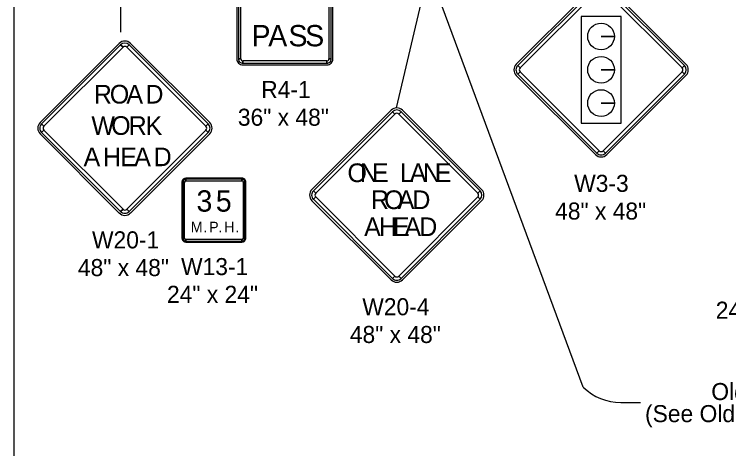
# Model space of a CAD drawing. Extents: x -2134934 to -2119606, y -2139046 to -2137036.
# Drawn here: x -2130232 to -2129562, y -2138285 to -2137877 of the extents above; entities that cross this region are included whole.
import ezdxf

# ---------------------------------------------------------------- set-up
doc = ezdxf.new("R2010")
doc.units = 0
for name, color, linetype in [('Default', 7, 'Continuous'), ('dsnStdLabel', 7, 'Continuous'), ('Level 2', 7, 'Continuous')]:
    doc.layers.add(name, color=color, linetype=linetype)

msp = doc.modelspace()

# ---------------------------------------------------------------- linework, layer by layer
at = {"layer": 'Default'}
msp.add_lwpolyline([(-2130231.95, -2137035.95), (-2127096.96, -2137035.95), (-2127096.96, -2139045.94), (-2130231.95, -2139045.94)], close=True, dxfattribs=at)
at = {"layer": 'dsnStdLabel'}
for p, q in [((-2130023.24, -2137810.29), (-2130023.24, -2137919.04)), ((-2129933.24, -2137919.04), (-2129933.24, -2137810.29)), ((-2129686.95, -2137849.65), (-2129761.19, -2137923.9)), ((-2129602.1, -2137923.9), (-2129676.34, -2137849.65)), ((-2129669.24, -2137897.87), (-2129681.74, -2137897.87)), ((-2129681.74, -2137897.87), (-2129669.24, -2137897.87)), ((-2130133.53, -2137904.4), (-2130207.78, -2137978.64)), ((-2130048.68, -2137978.64), (-2130122.92, -2137904.4)), ((-2130132.2, -2137905.72), (-2130129.99, -2137907.93)), ((-2130126.46, -2137907.93), (-2130124.25, -2137905.72)), ((-2130019.49, -2137919.04), (-2130021.68, -2137919.04)), ((-2130017.62, -2137923.1), (-2130017.62, -2137920.91)), ((-2130017.62, -2137924.66), (-2129938.87, -2137924.66)), ((-2129938.87, -2137920.91), (-2129938.87, -2137923.1)), ((-2129934.81, -2137919.04), (-2129936.99, -2137919.04)), ((-2129757.66, -2137927.43), (-2129759.87, -2137925.22)), ((-2129759.87, -2137933.18), (-2129757.66, -2137930.97)), ((-2129669.24, -2137929.12), (-2129681.74, -2137929.12)), ((-2129681.74, -2137929.12), (-2129669.24, -2137929.12)), ((-2129603.42, -2137925.22), (-2129605.63, -2137927.43)), ((-2129605.63, -2137930.97), (-2129603.42, -2137933.18)), ((-2129761.19, -2137934.5), (-2129686.95, -2138008.75)), ((-2129676.34, -2138008.75), (-2129602.1, -2137934.5)), ((-2129669.24, -2137960.37), (-2129681.74, -2137960.37)), ((-2129681.74, -2137960.37), (-2129669.24, -2137960.37)), ((-2129878.55, -2137967.13), (-2129952.8, -2138041.38)), ((-2129877.23, -2137968.46), (-2129875.02, -2137970.67)), ((-2129871.48, -2137970.67), (-2129869.27, -2137968.46)), ((-2129793.7, -2138041.38), (-2129867.95, -2137967.13)), ((-2130204.24, -2137982.18), (-2130206.45, -2137979.97)), ((-2130050, -2137979.97), (-2130052.21, -2137982.18)), ((-2130207.78, -2137989.25), (-2130133.53, -2138063.5)), ((-2130206.45, -2137987.92), (-2130204.24, -2137985.71)), ((-2130122.92, -2138063.5), (-2130048.68, -2137989.25)), ((-2130052.21, -2137985.71), (-2130050, -2137987.92)), ((-2129683.41, -2138005.21), (-2129685.62, -2138007.42)), ((-2129677.67, -2138007.42), (-2129679.88, -2138005.21)), ((-2130018.46, -2138030.77), (-2130070.95, -2138030.77)), ((-2130070.95, -2138033.27), (-2130070.95, -2138031.71)), ((-2130018.46, -2138031.71), (-2130018.46, -2138033.27)), ((-2130074.7, -2138034.52), (-2130074.7, -2138087.02)), ((-2130073.77, -2138034.52), (-2130072.2, -2138034.52)), ((-2130017.21, -2138034.52), (-2130015.64, -2138034.52)), ((-2130014.71, -2138087.02), (-2130014.71, -2138034.52)), ((-2129949.26, -2138044.91), (-2129951.47, -2138042.7)), ((-2129795.03, -2138042.7), (-2129797.23, -2138044.91)), ((-2129952.8, -2138051.98), (-2129878.55, -2138126.23)), ((-2129951.47, -2138050.66), (-2129949.26, -2138048.45)), ((-2129867.95, -2138126.23), (-2129793.7, -2138051.98)), ((-2129797.23, -2138048.45), (-2129795.03, -2138050.66)), ((-2130129.99, -2138059.96), (-2130132.2, -2138062.17)), ((-2130124.25, -2138062.17), (-2130126.46, -2138059.96)), ((-2130072.2, -2138087.02), (-2130073.77, -2138087.02)), ((-2130070.95, -2138089.83), (-2130070.95, -2138088.27)), ((-2130070.95, -2138090.77), (-2130018.46, -2138090.77)), ((-2130018.46, -2138088.27), (-2130018.46, -2138089.83)), ((-2130015.64, -2138087.02), (-2130017.21, -2138087.02)), ((-2129875.02, -2138122.69), (-2129877.23, -2138124.9)), ((-2129869.27, -2138124.9), (-2129871.48, -2138122.69))]:
    msp.add_line(p, q, dxfattribs=at)
for points in [[(-2130021.68, -2137810.29), (-2130021.68, -2137919.04), (-2130019.49, -2137919.04), (-2130019.49, -2137810.29), (-2130021.68, -2137810.29)], [(-2129934.81, -2137919.04), (-2129934.81, -2137810.29), (-2129936.99, -2137810.29), (-2129936.99, -2137919.04), (-2129934.81, -2137919.04)], [(-2129685.62, -2137850.98), (-2129759.87, -2137925.22), (-2129757.66, -2137927.43), (-2129683.41, -2137853.19), (-2129685.62, -2137850.98)], [(-2129603.42, -2137925.22), (-2129677.67, -2137850.98), (-2129679.88, -2137853.19), (-2129605.63, -2137927.43), (-2129603.42, -2137925.22)], [(-2129662.91, -2137879.26), (-2129700.38, -2137879.26), (-2129700.38, -2137979.15), (-2129662.91, -2137979.15), (-2129662.91, -2137879.26)], [(-2130132.2, -2137905.72), (-2130206.45, -2137979.97), (-2130204.24, -2137982.18), (-2130129.99, -2137907.93), (-2130132.2, -2137905.72)], [(-2130050, -2137979.97), (-2130124.25, -2137905.72), (-2130126.46, -2137907.93), (-2130052.21, -2137982.18), (-2130050, -2137979.97)], [(-2130017.62, -2137923.1), (-2129938.87, -2137923.1), (-2129938.87, -2137920.91), (-2130017.62, -2137920.91), (-2130017.62, -2137923.1)], [(-2129759.87, -2137933.18), (-2129685.62, -2138007.42), (-2129683.41, -2138005.21), (-2129757.66, -2137930.97), (-2129759.87, -2137933.18)], [(-2129677.67, -2138007.42), (-2129603.42, -2137933.18), (-2129605.63, -2137930.97), (-2129679.88, -2138005.21), (-2129677.67, -2138007.42)], [(-2129877.23, -2137968.46), (-2129951.47, -2138042.7), (-2129949.26, -2138044.91), (-2129875.02, -2137970.67), (-2129877.23, -2137968.46)], [(-2129795.03, -2138042.7), (-2129869.27, -2137968.46), (-2129871.48, -2137970.67), (-2129797.23, -2138044.91), (-2129795.03, -2138042.7)], [(-2130206.45, -2137987.92), (-2130132.2, -2138062.17), (-2130129.99, -2138059.96), (-2130204.24, -2137985.71), (-2130206.45, -2137987.92)], [(-2130124.25, -2138062.17), (-2130050, -2137987.92), (-2130052.21, -2137985.71), (-2130126.46, -2138059.96), (-2130124.25, -2138062.17)], [(-2130018.46, -2138031.71), (-2130070.95, -2138031.71), (-2130070.95, -2138033.27), (-2130018.46, -2138033.27), (-2130018.46, -2138031.71)], [(-2130073.77, -2138034.52), (-2130073.77, -2138087.02), (-2130072.2, -2138087.02), (-2130072.2, -2138034.52), (-2130073.77, -2138034.52)], [(-2130015.64, -2138087.02), (-2130015.64, -2138034.52), (-2130017.21, -2138034.52), (-2130017.21, -2138087.02), (-2130015.64, -2138087.02)], [(-2129951.47, -2138050.66), (-2129877.23, -2138124.9), (-2129875.02, -2138122.69), (-2129949.26, -2138048.45), (-2129951.47, -2138050.66)], [(-2129869.27, -2138124.9), (-2129795.03, -2138050.66), (-2129797.23, -2138048.45), (-2129871.48, -2138122.69), (-2129869.27, -2138124.9)], [(-2130070.95, -2138089.83), (-2130018.46, -2138089.83), (-2130018.46, -2138088.27), (-2130070.95, -2138088.27), (-2130070.95, -2138089.83)]]:
    msp.add_lwpolyline(points, close=True, dxfattribs=at)
for centre in [(-2129681.74, -2137897.87), (-2129681.74, -2137929.12), (-2129681.74, -2137960.37)]:
    msp.add_circle(centre, 12.5, dxfattribs=at)
for centre, radius, start, end in [((-2130128.23, -2137909.7), 7.5, 44.99999, 134.99974), ((-2130128.23, -2137909.7), 5.62, 44.99999, 134.99974), ((-2130128.23, -2137909.7), 2.5, 44.99999, 134.99974), ((-2130017.62, -2137919.04), 5.62, 179.99985, 270.00006), ((-2130017.62, -2137919.04), 4.06, 179.99985, 270.00006), ((-2130017.62, -2137919.04), 1.87, 179.99985, 270.00006), ((-2129938.87, -2137919.04), 5.62, 270.00006, 0.00027), ((-2129938.87, -2137919.04), 4.06, 270.00006, 0.00027), ((-2129938.87, -2137919.04), 1.87, 270.00006, 0.00027), ((-2129755.89, -2137929.2), 7.5, 134.99974, 224.99995), ((-2129607.4, -2137929.2), 7.5, 315.00016, 44.9998), ((-2129755.89, -2137929.2), 5.62, 134.99974, 224.99995), ((-2129755.89, -2137929.2), 2.5, 134.99974, 224.99995), ((-2129607.4, -2137929.2), 2.5, 315.00016, 44.9998), ((-2129607.4, -2137929.2), 5.62, 315.00016, 44.9998), ((-2129873.25, -2137972.43), 7.5, 44.99999, 134.99974), ((-2129873.25, -2137972.43), 5.62, 44.99999, 134.99974), ((-2129873.25, -2137972.43), 2.5, 44.99999, 134.99974), ((-2130202.47, -2137983.95), 7.5, 134.99974, 224.99995), ((-2130202.47, -2137983.95), 5.62, 134.99974, 224.99995), ((-2130202.47, -2137983.95), 2.5, 134.99974, 224.99995), ((-2130053.98, -2137983.95), 2.5, 315.00016, 44.9998), ((-2130053.98, -2137983.95), 5.62, 315.00016, 44.9998), ((-2130053.98, -2137983.95), 7.5, 315.00016, 44.9998), ((-2129681.64, -2138003.45), 7.5, 224.99995, 315.00016), ((-2129681.64, -2138003.45), 5.62, 224.99995, 315.00016), ((-2129681.64, -2138003.45), 2.5, 224.99995, 315.00016), ((-2130070.95, -2138034.52), 3.75, 90.00021, 179.99985), ((-2130070.95, -2138034.52), 2.81, 90.00021, 179.99985), ((-2130018.46, -2138034.52), 3.75, 0, 90.00021), ((-2130018.46, -2138034.52), 2.81, 0, 90.00021), ((-2130070.95, -2138034.52), 1.25, 90.00021, 179.99985), ((-2130018.46, -2138034.52), 1.25, 0, 90.00021), ((-2129947.49, -2138046.68), 7.5, 134.99974, 224.99995), ((-2129947.49, -2138046.68), 5.62, 134.99974, 224.99995), ((-2129947.49, -2138046.68), 2.5, 134.99974, 224.99995), ((-2129799, -2138046.68), 2.5, 315.00016, 44.9998), ((-2129799, -2138046.68), 5.62, 315.00016, 44.9998), ((-2129799, -2138046.68), 7.5, 315.00016, 44.9998), ((-2130128.23, -2138058.19), 7.5, 224.99995, 315.00016), ((-2130128.23, -2138058.19), 5.62, 224.99995, 315.00016), ((-2130128.23, -2138058.19), 2.5, 224.99995, 315.00016), ((-2130070.95, -2138087.02), 3.75, 179.99985, 270.00006), ((-2130070.95, -2138087.02), 2.81, 179.99985, 270.00006), ((-2130070.95, -2138087.02), 1.25, 179.99985, 270.00006), ((-2130018.46, -2138087.02), 3.75, 270.00006, 0.00027), ((-2130018.46, -2138087.02), 2.81, 270.00006, 0.00027), ((-2130018.46, -2138087.02), 1.25, 270.00006, 0.00027), ((-2129873.25, -2138120.93), 5.62, 224.99995, 315.00016), ((-2129873.25, -2138120.93), 2.5, 224.99995, 315.00016), ((-2129873.25, -2138120.93), 7.5, 224.99995, 315.00016)]:
    msp.add_arc(centre, radius, start, end, dxfattribs=at)
at = {"layer": 'Level 2'}
for p, q in [((-2129698.37, -2138226.89), (-2129892.38, -2137702.65)), ((-2130131.95, -2137893.97), (-2130131.95, -2137715.16)), ((-2129831.95, -2137785.16), (-2129873.72, -2137964.95)), ((-2129663.29, -2138241.26), (-2129644.83, -2138241.26))]:
    msp.add_line(p, q, dxfattribs=at)
msp.add_arc((-2129663.29, -2138191.26), 50, 225.43651, 270, dxfattribs=at)

# ---------------------------------------------------------------- texts
at = {"layer": 'dsnStdLabel'}
for s, height, p in [('P', 20, (-2130009.51, -2137907.17)), ('A', 20, (-2129993.82, -2137907.17)), ('S', 20, (-2129974.85, -2137907.17)), ('S', 20, (-2129959.17, -2137907.17)), ('R', 17.5, (-2130157.39, -2137960.82)), ('O', 17.5, (-2130142.38, -2137960.82)), ('A', 17.5, (-2130126.83, -2137960.82)), ('D', 17.5, (-2130108.95, -2137960.82)), ('R4-1', 16, (-2130000.41, -2137955.66)), ('36" x 48"', 16, (-2130022.31, -2137981.66)), ('W', 17.5, (-2130159.67, -2137990.2)), ('O', 17.5, (-2130141.08, -2137990.2)), ('R', 17.5, (-2130124.67, -2137990.2)), ('K', 17.5, (-2130108.81, -2137990.2)), ('A', 17.5, (-2130166.95, -2138019.57)), ('H', 17.5, (-2130148.74, -2138019.57)), ('E', 17.5, (-2130132.51, -2138019.57)), ('A', 17.5, (-2130119.47, -2138019.57)), ('D', 17.5, (-2130101.26, -2138019.57)), ('O', 17.5, (-2129919.53, -2138034.49)), ('N', 17.5, (-2129907.76, -2138034.49)), ('E', 17.5, (-2129896.53, -2138034.49)), ('L', 17.5, (-2129870.28, -2138034.49)), ('A', 17.5, (-2129861.08, -2138034.49)), ('N', 17.5, (-2129848.82, -2138034.49)), ('E', 17.5, (-2129837.59, -2138034.49)), ('W3-3', 16, (-2129706.94, -2138043.67)), ('3', 20, (-2130061.09, -2138062.23)), ('5', 20, (-2130042.97, -2138062.23)), ('R', 17.5, (-2129897.43, -2138059.8)), ('O', 17.5, (-2129885.14, -2138059.8)), ('A', 17.5, (-2129872.3, -2138059.8)), ('D', 17.5, (-2129858.64, -2138059.8)), ('48" x 48"', 16, (-2129724.81, -2138069.67)), ('M', 10, (-2130066.48, -2138081.71)), ('P', 10, (-2130049.23, -2138081.71)), ('H', 10, (-2130035.11, -2138081.71)), ('A', 17.5, (-2129903.86, -2138085.12)), ('H', 17.5, (-2129890, -2138085.12)), ('E', 17.5, (-2129876.78, -2138085.12)), ('A', 17.5, (-2129866.07, -2138085.12)), ('D', 17.5, (-2129852.2, -2138085.12)), ('W20-1', 16, (-2130159.08, -2138096.69)), ('.', 10, (-2130054.68, -2138081.71)), ('.', 10, (-2130040.57, -2138081.71)), ('.', 10, (-2130024.64, -2138081.71)), ('W13-1', 16, (-2130075.56, -2138121.77)), ('48" x 48"', 16, (-2130172.29, -2138122.69)), ('24" x 24"', 16, (-2130088.77, -2138147.77)), ('W20-4', 16, (-2129905.62, -2138159.43)), ('24" x 36"', 16, (-2129574.18, -2138162.65)), ('48" x 48"', 16, (-2129917.32, -2138185.43))]:
    msp.add_text(s, height=height, dxfattribs=at).set_placement(p)
at = {"layer": 'Level 2'}
for s, p in [('Old Hwy 2 (To Remain Open)', (-2129578.36, -2138238.97)), ('(See Old Hwy 2 Advanced Signing on J.5)', (-2129640.51, -2138259.67))]:
    msp.add_text(s, height=16, dxfattribs=at).set_placement(p)

doc.saveas('drawing.dxf')
